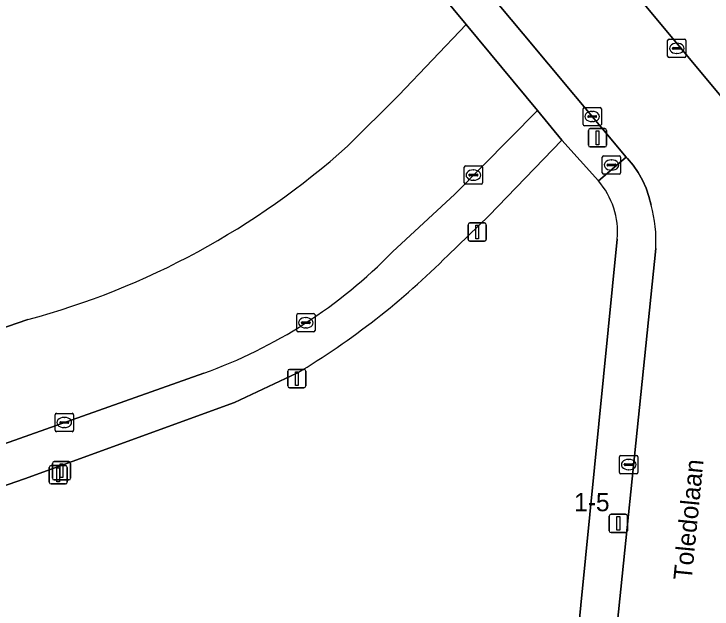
# Model space of a CAD drawing. Extents: x 159451 to 160664, y 388402 to 389723.
# Drawn here: x 159702.07 to 159740.16, y 389033.61 to 389066.08 of the extents above; entities that cross this region are included whole.
import ezdxf

# ---------------------------------------------------------------- set-up
doc = ezdxf.new("R2010")
doc.units = 0
for name, color, linetype in [('IMGEO_Brandkraan', 7, 'Continuous'), ('IMGEO_Groenvoorziening', 7, 'Continuous'), ('IMGEO_Kolk', 7, 'Continuous'), ('IMGEO_Lichtmast', 7, 'Continuous'), ('IMGEO_Openbare_ruimte_label', 7, 'Continuous'), ('IMGEO_Pand_nummerreeks', 7, 'Continuous'), ('IMGEO_Rijbaan_lokaal_open', 7, 'Continuous'), ('IMGEO_Voetpad_open', 7, 'Continuous')]:
    doc.layers.add(name, color=color, linetype=linetype)

msp = doc.modelspace()

# ---------------------------------------------------------------- linework, layer by layer
at = {"layer": 'IMGEO_Brandkraan'}
for p, q in [((159734.169, 389057.413), (159734.169, 389058.265)), ((159734.244, 389058.339), (159735.096, 389058.339)), ((159734.657, 389058.119), (159734.682, 389058.119)), ((159735.17, 389058.265), (159735.17, 389057.413)), ((159734.428, 389057.833), (159734.428, 389057.845)), ((159734.866, 389057.796), (159734.468, 389057.796)), ((159734.471, 389057.882), (159734.869, 389057.882)), ((159734.912, 389057.845), (159734.912, 389057.833)), ((159735.096, 389057.339), (159734.244, 389057.339)), ((159734.68, 389057.559), (159734.655, 389057.559))]:
    msp.add_line(p, q, dxfattribs=at)
for points in [[(159734.169, 389057.413), (159734.169, 389058.265)], [(159734.244, 389058.339), (159735.096, 389058.339)], [(159735.17, 389058.265), (159735.17, 389057.413)], [(159735.096, 389057.339), (159734.244, 389057.339)]]:
    msp.add_lwpolyline(points, dxfattribs=at)
for centre, radius, start, end in [((159734.246, 389058.263), 0.0765, 91.552, 178.448), ((159734.246, 389058.263), 0.0765, 91.552, 178.448), ((159735.094, 389058.263), 0.0765, 1.552, 88.448), ((159735.094, 389058.263), 0.0765, 1.552, 88.448), ((159734.468, 389057.842), 0.0403, 85.8775, 175.7526), ((159734.465, 389057.832), 0.0366, 178.938, 274.7102), ((159734.869, 389057.839), 0.043, 264.8664, 352.4533), ((159734.873, 389057.844), 0.0386, 1.7309, 96.639), ((159734.246, 389057.415), 0.0765, 181.552, 268.448), ((159734.246, 389057.415), 0.0765, 181.552, 268.448), ((159735.094, 389057.415), 0.0765, 271.552, 358.448), ((159735.094, 389057.415), 0.0765, 271.552, 358.448)]:
    msp.add_arc(centre, radius, start, end, dxfattribs=at)
for centre, major_axis, ratio, start_param, end_param in [((159734.656, 389057.839), (-0.387, 0.002), 0.722429, 4.712389, 7.853982), ((159734.681, 389057.839), (-0.39, 0.002), 0.717154, 1.570796, 4.712389)]:
    msp.add_ellipse(centre, major_axis=major_axis, ratio=ratio, start_param=start_param, end_param=end_param, dxfattribs=at)
at = {"layer": 'IMGEO_Groenvoorziening'}
for points in [[(159720.262, 389058.863), (159723.067, 389061.645), (159726.74, 389065.51), (159703.16, 389093.947)], [(159733.958, 389056.98), (159731.964, 389059.199), (159727.978, 389055.076), (159725.746, 389052.911)], [(159732.25, 389026.319), (159734.987, 389053.802)], [(159700.012, 389048.455), (159702.837, 389049.408)], [(159717.499, 389046.477), (159714.104, 389044.886), (159702.65, 389040.726), (159696.858, 389038.718), (159691.615, 389036.62), (159687.227, 389034.723)]]:
    msp.add_lwpolyline(points, dxfattribs=at)
for centre, radius, start, end in [((159691.72, 389090.679), 42.742, 285.0751, 311.8944), ((159730.668, 389054.159), 4.334, 355.2716, 40.6111), ((159695.803, 389082.789), 42.3, 300.8579, 315.0621)]:
    msp.add_arc(centre, radius, start, end, dxfattribs=at)
at = {"layer": 'IMGEO_Kolk'}
for p, q in [((159737.733, 389063.778), (159737.733, 389064.63)), ((159737.808, 389064.704), (159738.66, 389064.704)), ((159738.221, 389064.484), (159738.246, 389064.484)), ((159738.734, 389064.63), (159738.734, 389063.778)), ((159737.992, 389064.198), (159737.992, 389064.21)), ((159738.43, 389064.161), (159738.032, 389064.161)), ((159738.035, 389064.247), (159738.433, 389064.247)), ((159738.476, 389064.21), (159738.476, 389064.198)), ((159738.66, 389063.704), (159737.808, 389063.704)), ((159738.244, 389063.924), (159738.219, 389063.924)), ((159733.117, 389060.059), (159733.117, 389060.911)), ((159733.192, 389060.985), (159734.044, 389060.985)), ((159733.605, 389060.765), (159733.63, 389060.765)), ((159734.118, 389060.911), (159734.118, 389060.059)), ((159733.376, 389060.479), (159733.376, 389060.491)), ((159733.814, 389060.442), (159733.416, 389060.442)), ((159733.419, 389060.528), (159733.817, 389060.528)), ((159733.86, 389060.491), (159733.86, 389060.479)), ((159734.044, 389059.985), (159733.192, 389059.985)), ((159733.628, 389060.205), (159733.603, 389060.205)), ((159726.638, 389056.864), (159726.638, 389057.716)), ((159726.713, 389057.79), (159727.565, 389057.79)), ((159727.639, 389057.716), (159727.639, 389056.864)), ((159726.897, 389057.284), (159726.897, 389057.296)), ((159727.335, 389057.247), (159726.937, 389057.247)), ((159726.94, 389057.333), (159727.338, 389057.333)), ((159727.126, 389057.57), (159727.151, 389057.57)), ((159727.381, 389057.296), (159727.381, 389057.284)), ((159727.149, 389057.01), (159727.124, 389057.01)), ((159727.565, 389056.79), (159726.713, 389056.79)), ((159717.496, 389048.806), (159717.496, 389049.658)), ((159717.571, 389049.732), (159718.423, 389049.732)), ((159718.497, 389049.658), (159718.497, 389048.806)), ((159717.755, 389049.226), (159717.755, 389049.238)), ((159717.798, 389049.275), (159718.196, 389049.275)), ((159717.984, 389049.512), (159718.009, 389049.512)), ((159718.239, 389049.238), (159718.239, 389049.226)), ((159718.193, 389049.189), (159717.795, 389049.189)), ((159718.007, 389048.952), (159717.982, 389048.952)), ((159718.423, 389048.732), (159717.571, 389048.732)), ((159704.392, 389044.291), (159705.244, 389044.291)), ((159704.317, 389043.365), (159704.317, 389044.217)), ((159704.805, 389044.071), (159704.83, 389044.071)), ((159705.318, 389044.217), (159705.318, 389043.365)), ((159704.576, 389043.785), (159704.576, 389043.797)), ((159705.014, 389043.748), (159704.616, 389043.748)), ((159704.619, 389043.834), (159705.017, 389043.834)), ((159704.828, 389043.511), (159704.803, 389043.511)), ((159705.06, 389043.797), (159705.06, 389043.785)), ((159705.244, 389043.291), (159704.392, 389043.291)), ((159735.185, 389041.995), (159736.037, 389041.995)), ((159735.11, 389041.069), (159735.11, 389041.921)), ((159735.598, 389041.775), (159735.623, 389041.775)), ((159736.111, 389041.921), (159736.111, 389041.069)), ((159735.369, 389041.489), (159735.369, 389041.501)), ((159735.807, 389041.452), (159735.409, 389041.452)), ((159735.412, 389041.538), (159735.81, 389041.538)), ((159735.853, 389041.501), (159735.853, 389041.489)), ((159736.037, 389040.995), (159735.185, 389040.995)), ((159735.621, 389041.215), (159735.596, 389041.215))]:
    msp.add_line(p, q, dxfattribs=at)
for points in [[(159737.733, 389063.778), (159737.733, 389064.63)], [(159737.808, 389064.704), (159738.66, 389064.704)], [(159738.734, 389064.63), (159738.734, 389063.778)], [(159738.66, 389063.704), (159737.808, 389063.704)], [(159733.117, 389060.059), (159733.117, 389060.911)], [(159733.192, 389060.985), (159734.044, 389060.985)], [(159734.118, 389060.911), (159734.118, 389060.059)], [(159734.044, 389059.985), (159733.192, 389059.985)], [(159726.638, 389056.864), (159726.638, 389057.716)], [(159726.713, 389057.79), (159727.565, 389057.79)], [(159727.639, 389057.716), (159727.639, 389056.864)], [(159727.565, 389056.79), (159726.713, 389056.79)], [(159717.496, 389048.806), (159717.496, 389049.658)], [(159717.571, 389049.732), (159718.423, 389049.732)], [(159718.497, 389049.658), (159718.497, 389048.806)], [(159718.423, 389048.732), (159717.571, 389048.732)], [(159704.392, 389044.291), (159705.244, 389044.291)], [(159704.317, 389043.365), (159704.317, 389044.217)], [(159705.318, 389044.217), (159705.318, 389043.365)], [(159705.244, 389043.291), (159704.392, 389043.291)], [(159735.185, 389041.995), (159736.037, 389041.995)], [(159735.11, 389041.069), (159735.11, 389041.921)], [(159736.111, 389041.921), (159736.111, 389041.069)], [(159736.037, 389040.995), (159735.185, 389040.995)]]:
    msp.add_lwpolyline(points, dxfattribs=at)
for centre, radius, start, end in [((159737.81, 389064.628), 0.0765, 91.552, 178.448), ((159737.81, 389064.628), 0.0765, 91.552, 178.448), ((159738.658, 389064.628), 0.0765, 1.552, 88.448), ((159738.658, 389064.628), 0.0765, 1.552, 88.448), ((159738.032, 389064.207), 0.0403, 85.8775, 175.7526), ((159738.029, 389064.197), 0.0366, 178.938, 274.7102), ((159738.433, 389064.204), 0.043, 264.8664, 352.4533), ((159738.437, 389064.209), 0.0386, 1.7309, 96.639), ((159737.81, 389063.78), 0.0765, 181.552, 268.448), ((159737.81, 389063.78), 0.0765, 181.552, 268.448), ((159738.658, 389063.78), 0.0765, 271.552, 358.448), ((159738.658, 389063.78), 0.0765, 271.552, 358.448), ((159733.194, 389060.909), 0.0765, 91.552, 178.448), ((159733.194, 389060.909), 0.0765, 91.552, 178.448), ((159734.042, 389060.909), 0.0765, 1.552, 88.448), ((159734.042, 389060.909), 0.0765, 1.552, 88.448), ((159733.416, 389060.488), 0.0403, 85.8775, 175.7526), ((159733.413, 389060.478), 0.0366, 178.938, 274.7102), ((159733.817, 389060.485), 0.043, 264.8664, 352.4533), ((159733.821, 389060.49), 0.0386, 1.7309, 96.639), ((159733.194, 389060.061), 0.0765, 181.552, 268.448), ((159733.194, 389060.061), 0.0765, 181.552, 268.448), ((159734.042, 389060.061), 0.0765, 271.552, 358.448), ((159734.042, 389060.061), 0.0765, 271.552, 358.448), ((159726.715, 389057.714), 0.0765, 91.552, 178.448), ((159726.715, 389057.714), 0.0765, 91.552, 178.448), ((159727.563, 389057.714), 0.0765, 1.552, 88.448), ((159727.563, 389057.714), 0.0765, 1.552, 88.448), ((159726.937, 389057.293), 0.0403, 85.8775, 175.7526), ((159726.934, 389057.283), 0.0366, 178.938, 274.7102), ((159727.338, 389057.29), 0.043, 264.8664, 352.4533), ((159727.342, 389057.295), 0.0386, 1.7309, 96.639), ((159726.715, 389056.866), 0.0765, 181.552, 268.448), ((159726.715, 389056.866), 0.0765, 181.552, 268.448), ((159727.563, 389056.866), 0.0765, 271.552, 358.448), ((159727.563, 389056.866), 0.0765, 271.552, 358.448), ((159717.573, 389049.656), 0.0765, 91.552, 178.448), ((159717.573, 389049.656), 0.0765, 91.552, 178.448), ((159718.421, 389049.656), 0.0765, 1.552, 88.448), ((159718.421, 389049.656), 0.0765, 1.552, 88.448), ((159717.795, 389049.235), 0.0403, 85.8775, 175.7526), ((159717.792, 389049.225), 0.0366, 178.938, 274.7102), ((159718.196, 389049.232), 0.043, 264.8664, 352.4533), ((159718.2, 389049.237), 0.0386, 1.7309, 96.639), ((159717.573, 389048.808), 0.0765, 181.552, 268.448), ((159717.573, 389048.808), 0.0765, 181.552, 268.448), ((159718.421, 389048.808), 0.0765, 271.552, 358.448), ((159718.421, 389048.808), 0.0765, 271.552, 358.448), ((159704.394, 389044.215), 0.0765, 91.552, 178.448), ((159704.394, 389044.215), 0.0765, 91.552, 178.448), ((159705.242, 389044.215), 0.0765, 1.552, 88.448), ((159705.242, 389044.215), 0.0765, 1.552, 88.448), ((159704.616, 389043.794), 0.0403, 85.8775, 175.7526), ((159704.613, 389043.784), 0.0366, 178.938, 274.7102), ((159705.017, 389043.791), 0.043, 264.8664, 352.4533), ((159705.021, 389043.796), 0.0386, 1.7309, 96.639), ((159704.394, 389043.367), 0.0765, 181.552, 268.448), ((159704.394, 389043.367), 0.0765, 181.552, 268.448), ((159705.242, 389043.367), 0.0765, 271.552, 358.448), ((159705.242, 389043.367), 0.0765, 271.552, 358.448), ((159735.187, 389041.919), 0.0765, 91.552, 178.448), ((159735.187, 389041.919), 0.0765, 91.552, 178.448), ((159736.035, 389041.919), 0.0765, 1.552, 88.448), ((159736.035, 389041.919), 0.0765, 1.552, 88.448), ((159735.409, 389041.498), 0.0403, 85.8775, 175.7526), ((159735.406, 389041.488), 0.0366, 178.938, 274.7102), ((159735.81, 389041.495), 0.043, 264.8664, 352.4533), ((159735.814, 389041.5), 0.0386, 1.7309, 96.639), ((159735.187, 389041.071), 0.0765, 181.552, 268.448), ((159735.187, 389041.071), 0.0765, 181.552, 268.448), ((159736.035, 389041.071), 0.0765, 271.552, 358.448), ((159736.035, 389041.071), 0.0765, 271.552, 358.448)]:
    msp.add_arc(centre, radius, start, end, dxfattribs=at)
for centre, major_axis, ratio, start_param, end_param in [((159738.22, 389064.204), (-0.387, 0.002), 0.722429, 4.712389, 7.853982), ((159738.245, 389064.204), (-0.39, 0.002), 0.717154, 1.570796, 4.712389), ((159733.604, 389060.485), (-0.387, 0.002), 0.722429, 4.712389, 7.853982), ((159733.629, 389060.485), (-0.39, 0.002), 0.717154, 1.570796, 4.712389), ((159727.125, 389057.29), (-0.387, 0.002), 0.722429, 4.712389, 7.853982), ((159727.15, 389057.29), (-0.39, 0.002), 0.717154, 1.570796, 4.712389), ((159717.983, 389049.232), (-0.387, 0.002), 0.722429, 4.712389, 7.853982), ((159718.008, 389049.232), (-0.39, 0.002), 0.717154, 1.570796, 4.712389), ((159704.804, 389043.791), (-0.387, 0.002), 0.722429, 4.712389, 7.853982), ((159704.829, 389043.791), (-0.39, 0.002), 0.717154, 1.570796, 4.712389), ((159735.597, 389041.495), (-0.387, 0.002), 0.722429, 4.712389, 7.853982), ((159735.622, 389041.495), (-0.39, 0.002), 0.717154, 1.570796, 4.712389)]:
    msp.add_ellipse(centre, major_axis=major_axis, ratio=ratio, start_param=start_param, end_param=end_param, dxfattribs=at)
at = {"layer": 'IMGEO_Lichtmast'}
for p, q in [((159733.411, 389058.923), (159733.411, 389059.723)), ((159733.411, 389059.723), (159733.411, 389058.923)), ((159733.511, 389059.823), (159734.301, 389059.823)), ((159734.301, 389059.823), (159733.511, 389059.823)), ((159734.401, 389059.723), (159734.401, 389058.923)), ((159734.401, 389058.923), (159734.401, 389059.723)), ((159734.301, 389058.823), (159733.511, 389058.823)), ((159733.511, 389058.823), (159734.301, 389058.823)), ((159726.847, 389053.784), (159726.847, 389054.584)), ((159726.847, 389054.584), (159726.847, 389053.784)), ((159726.947, 389054.684), (159727.737, 389054.684)), ((159727.737, 389054.684), (159726.947, 389054.684)), ((159727.837, 389054.584), (159727.837, 389053.784)), ((159727.837, 389053.784), (159727.837, 389054.584)), ((159727.737, 389053.684), (159726.947, 389053.684)), ((159726.947, 389053.684), (159727.737, 389053.684)), ((159717.006, 389045.786), (159717.006, 389046.586)), ((159717.006, 389046.586), (159717.006, 389045.786)), ((159717.106, 389046.686), (159717.896, 389046.686)), ((159717.896, 389046.686), (159717.106, 389046.686)), ((159717.996, 389046.586), (159717.996, 389045.786)), ((159717.996, 389045.786), (159717.996, 389046.586)), ((159717.896, 389045.686), (159717.106, 389045.686)), ((159717.106, 389045.686), (159717.896, 389045.686)), ((159704.273, 389041.656), (159705.063, 389041.656)), ((159705.063, 389041.656), (159704.273, 389041.656)), ((159703.995, 389040.537), (159703.995, 389041.337)), ((159703.995, 389041.337), (159703.995, 389040.537)), ((159704.095, 389041.437), (159704.885, 389041.437)), ((159704.885, 389041.437), (159704.095, 389041.437)), ((159704.173, 389040.756), (159704.173, 389041.556)), ((159704.173, 389041.556), (159704.173, 389040.756)), ((159704.985, 389041.337), (159704.985, 389040.537)), ((159704.985, 389040.537), (159704.985, 389041.337)), ((159705.163, 389041.556), (159705.163, 389040.756)), ((159705.163, 389040.756), (159705.163, 389041.556)), ((159705.063, 389040.656), (159704.273, 389040.656)), ((159704.273, 389040.656), (159705.063, 389040.656)), ((159704.885, 389040.437), (159704.095, 389040.437)), ((159704.095, 389040.437), (159704.885, 389040.437)), ((159734.548, 389037.886), (159734.548, 389038.686)), ((159734.548, 389038.686), (159734.548, 389037.886)), ((159734.648, 389038.786), (159735.438, 389038.786)), ((159735.438, 389038.786), (159734.648, 389038.786)), ((159735.538, 389038.686), (159735.538, 389037.886)), ((159735.538, 389037.886), (159735.538, 389038.686)), ((159735.438, 389037.786), (159734.648, 389037.786)), ((159734.648, 389037.786), (159735.438, 389037.786))]:
    msp.add_line(p, q, dxfattribs=at)
for points in [[(159733.831, 389059.698), (159733.981, 389059.698), (159733.981, 389058.948), (159733.831, 389058.948), (159733.831, 389059.698)], [(159727.267, 389054.559), (159727.417, 389054.559), (159727.417, 389053.809), (159727.267, 389053.809), (159727.267, 389054.559)], [(159717.426, 389046.561), (159717.576, 389046.561), (159717.576, 389045.811), (159717.426, 389045.811), (159717.426, 389046.561)], [(159704.415, 389041.312), (159704.565, 389041.312), (159704.565, 389040.562), (159704.415, 389040.562), (159704.415, 389041.312)], [(159704.593, 389041.531), (159704.743, 389041.531), (159704.743, 389040.781), (159704.593, 389040.781), (159704.593, 389041.531)], [(159734.968, 389038.661), (159735.118, 389038.661), (159735.118, 389037.911), (159734.968, 389037.911), (159734.968, 389038.661)]]:
    msp.add_lwpolyline(points, dxfattribs=at)
for centre, start, end in [((159733.511, 389059.723), 90, 180), ((159733.511, 389059.723), 90, 180), ((159734.301, 389059.723), 0, 90), ((159734.301, 389059.723), 360, 90), ((159733.511, 389058.923), 180, 270), ((159733.511, 389058.923), 180, 270), ((159734.301, 389058.923), 270, 0), ((159734.301, 389058.923), 270, 0), ((159726.947, 389054.584), 90, 180), ((159726.947, 389054.584), 90, 180), ((159727.737, 389054.584), 0, 90), ((159727.737, 389054.584), 360, 90), ((159726.947, 389053.784), 180, 270), ((159726.947, 389053.784), 180, 270), ((159727.737, 389053.784), 270, 0), ((159727.737, 389053.784), 270, 0), ((159717.106, 389046.586), 90, 180), ((159717.106, 389046.586), 90, 180), ((159717.896, 389046.586), 0, 90), ((159717.896, 389046.586), 360, 90), ((159717.106, 389045.786), 180, 270), ((159717.106, 389045.786), 180, 270), ((159717.896, 389045.786), 270, 0), ((159717.896, 389045.786), 270, 0), ((159704.273, 389041.556), 90, 180), ((159704.273, 389041.556), 90, 180), ((159705.063, 389041.556), 0, 90), ((159705.063, 389041.556), 360, 90), ((159704.095, 389041.337), 90, 180), ((159704.095, 389041.337), 90, 180), ((159704.885, 389041.337), 0, 90), ((159704.885, 389041.337), 360, 90), ((159704.095, 389040.537), 180, 270), ((159704.095, 389040.537), 180, 270), ((159704.273, 389040.756), 180, 270), ((159704.273, 389040.756), 180, 270), ((159704.885, 389040.537), 270, 0), ((159704.885, 389040.537), 270, 0), ((159705.063, 389040.756), 270, 0), ((159705.063, 389040.756), 270, 0), ((159734.648, 389038.686), 90, 180), ((159734.648, 389038.686), 90, 180), ((159735.438, 389038.686), 0, 90), ((159735.438, 389038.686), 360, 90), ((159734.648, 389037.886), 180, 270), ((159734.648, 389037.886), 180, 270), ((159735.438, 389037.886), 270, 0), ((159735.438, 389037.886), 270, 0)]:
    msp.add_arc(centre, 0.1, start, end, dxfattribs=at)
at = {"layer": 'IMGEO_Rijbaan_lokaal_open'}
for points in [[(159680.802, 389128.304), (159682.577, 389125.009), (159685.913, 389118.942), (159688.727, 389114.585), (159691.92, 389110.497), (159694.035, 389108.156), (159705.801, 389093.82), (159708.515, 389090.5), (159729.843, 389064.997), (159735.475, 389058.272), (159735.544, 389058.197), (159735.85, 389057.826), (159736.122, 389057.43), (159736.358, 389057.01), (159736.555, 389056.572), (159736.712, 389056.117), (159736.827, 389055.651)], [(159712.143, 389095.814), (159740.742, 389061.477), (159742.318, 389058.742), (159743.13, 389055.644), (159743.132, 389053.016), (159740.22, 389024.649), (159739.859, 389023.068), (159738.949, 389020.892), (159737.694, 389018.927), (159736.552, 389017.776), (159722.021, 389006.481), (159724.025, 389005.973), (159725.749, 389005.536)], [(159713.77, 389000), (159716.46, 389002.147), (159722.021, 389006.481), (159736.552, 389017.776), (159737.694, 389018.927), (159738.949, 389020.892), (159739.859, 389023.068), (159740.22, 389024.649), (159743.132, 389053.016), (159743.13, 389055.644), (159742.318, 389058.742), (159740.742, 389061.477), (159712.143, 389095.814)], [(159722.729, 389053.098), (159726.131, 389056.253), (159730.625, 389060.817), (159726.74, 389065.51), (159723.067, 389061.645), (159720.262, 389058.863)], [(159737.083, 389053.28), (159734.226, 389025.499)], [(159702.837, 389049.408), (159700.012, 389048.455), (159699.896, 389048.403), (159689.467, 389044.483), (159683.954, 389042.107), (159683.811, 389042.03), (159672.756, 389037.477), (159672.696, 389037.46), (159664.635, 389034.331), (159664.437, 389034.233), (159653.757, 389029.873), (159650.493, 389028.426), (159651.773, 389021.385), (159653.064, 389014.277), (159653.934, 389009.489)], [(159691.434, 389038.813), (159697.167, 389041.076), (159712.428, 389046.481)]]:
    msp.add_lwpolyline(points, dxfattribs=at)
for centre, radius, start, end in [((159691.72, 389090.679), 42.742, 285.0751, 311.8944), ((159729.982, 389053.713), 7.114, 356.5141, 15.8107), ((159703.19, 389072.189), 27.318, 289.766, 315.6646)]:
    msp.add_arc(centre, radius, start, end, dxfattribs=at)
at = {"layer": 'IMGEO_Voetpad_open'}
msp.add_lwpolyline([(159708.515, 389090.5), (159705.801, 389093.82), (159694.035, 389108.156), (159691.92, 389110.497), (159688.727, 389114.585), (159685.913, 389118.942), (159682.577, 389125.009), (159680.732, 389124.411), (159685.457, 389116.057), (159693.619, 389105.303), (159694.257, 389104.63), (159700.795, 389096.787), (159703.16, 389093.947), (159726.74, 389065.51), (159730.625, 389060.817), (159731.964, 389059.199), (159733.958, 389056.98), (159735.475, 389058.272), (159729.843, 389064.997)], close=True, dxfattribs=at)
for points in [[(159725.746, 389052.911), (159727.978, 389055.076), (159731.964, 389059.199), (159730.625, 389060.817), (159726.131, 389056.253), (159722.729, 389053.098)], [(159736.827, 389055.651), (159736.712, 389056.117), (159736.555, 389056.572), (159736.358, 389057.01), (159736.122, 389057.43), (159735.85, 389057.826), (159735.544, 389058.197), (159735.475, 389058.272), (159733.958, 389056.98)], [(159734.987, 389053.802), (159732.25, 389026.319)], [(159734.226, 389025.499), (159737.083, 389053.28)], [(159712.428, 389046.481), (159697.167, 389041.076), (159691.434, 389038.813), (159676.353, 389032.432), (159668.491, 389029.41)], [(159687.227, 389034.723), (159691.615, 389036.62), (159696.858, 389038.718), (159702.65, 389040.726), (159714.104, 389044.886), (159717.499, 389046.477)]]:
    msp.add_lwpolyline(points, dxfattribs=at)
for centre, radius, start, end in [((159730.668, 389054.159), 4.334, 355.2716, 40.6111), ((159729.982, 389053.713), 7.114, 356.5141, 15.8107), ((159703.19, 389072.189), 27.318, 289.766, 315.6646), ((159695.803, 389082.789), 42.3, 300.8579, 315.0621)]:
    msp.add_arc(centre, radius, start, end, dxfattribs=at)

# ---------------------------------------------------------------- texts
at = {"layer": 'IMGEO_Openbare_ruimte_label'}
msp.add_text('Toledolaan', height=1, rotation=84.3179, dxfattribs=at).set_placement((159739.039, 389035.148))
at = {"layer": 'IMGEO_Pand_nummerreeks'}
msp.add_text('1-5', height=1, dxfattribs=at).set_placement((159732.632, 389038.948))

doc.saveas('drawing.dxf')
